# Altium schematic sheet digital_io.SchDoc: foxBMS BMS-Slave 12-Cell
size A3; DocumentNumber: 8; SheetNumber: 8; SheetTotal: 15; AUTHOR: Fraunhofer IISB foxBMS Team; SheetDescription: Primary Digital Inputs/Outputs
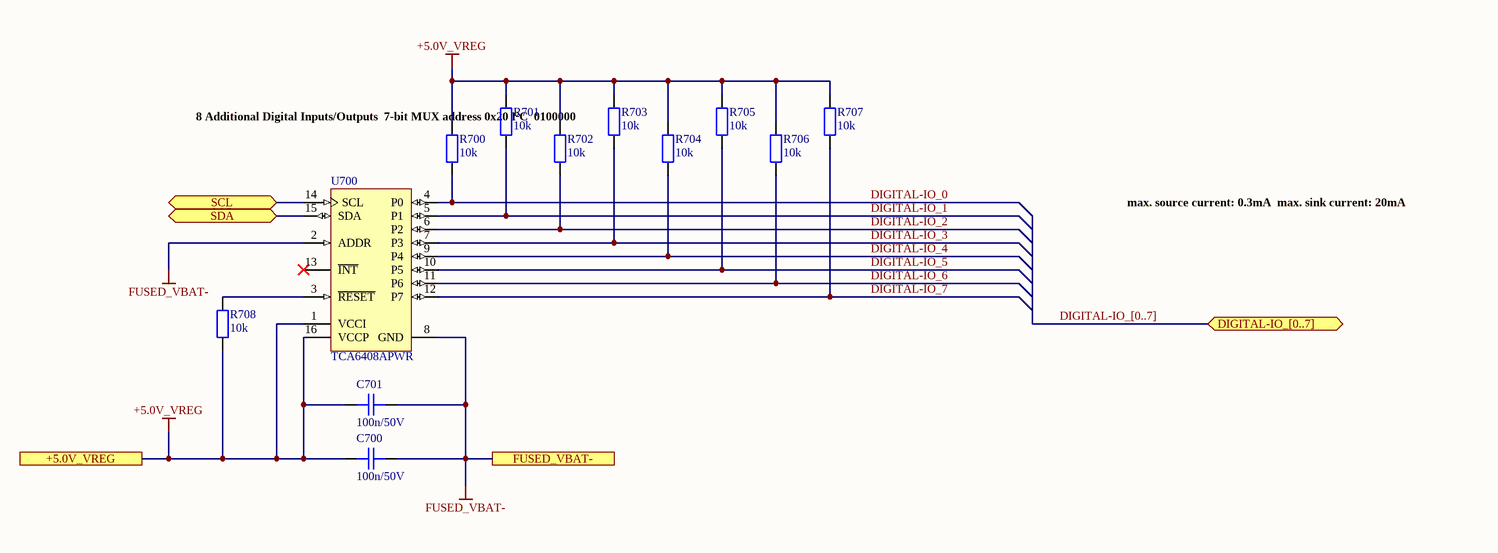
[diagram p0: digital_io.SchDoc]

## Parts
C700  100n/50V  [CAPC1608X08N]
C701  100n/50V  [CAPC1608X08N]
R700  10k  [RESC1608X05N]
R701  10k  [RESC1608X05N]
R702  10k  [RESC1608X05N]
R703  10k  [RESC1608X05N]
R704  10k  [RESC1608X05N]
R705  10k  [RESC1608X05N]
R706  10k  [RESC1608X05N]
R707  10k  [RESC1608X05N]
R708  10k  [RESC1608X05N]
U700  TCA6408APWR  [PW0016A_L]

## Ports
+5.0V_VREG, DIGITAL-IO_[0..7] (bidir), FUSED_VBAT-, SCL (bidir), SDA (bidir)

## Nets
+5.0V_VREG: C700.2 C701.2 R700.2 R701.2 R702.2 R703.2 R704.2 R705.2 R706.2 R707.2 R708.1 U700.1(VCCI) U700.16(VCCP) ; port +5.0V_VREG
FUSED_VBAT-: C700.1 C701.1 U700.2(ADDR) U700.8(GND) ; port FUSED_VBAT-
DIGITAL-IO_0: R700.1 U700.4(P0)
DIGITAL-IO_1: R701.1 U700.5(P1)
DIGITAL-IO_2: R702.1 U700.6(P2)
DIGITAL-IO_3: R703.1 U700.7(P3)
DIGITAL-IO_4: R704.1 U700.9(P4)
DIGITAL-IO_5: R705.1 U700.10(P5)
DIGITAL-IO_6: R706.1 U700.11(P6)
DIGITAL-IO_7: R707.1 U700.12(P7)
SCL: U700.14(SCL) ; port SCL
SDA: U700.15(SDA) ; port SDA
NetR708_2: R708.2 U700.3(~{RESET})

Not connected (* = marked no-connect by the designer): U700 13(~{INT})*

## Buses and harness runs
bus DIGITAL-IO_[0..7] = port DIGITAL-IO_[0..7]

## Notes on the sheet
- 8 Additional Digital Inputs/Outputs
  7-bit MUX address 0x20 I²C
  0100000
- max. source current: 0.3mA
  max. sink current: 20mA

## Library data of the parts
C700 C701 = gen_C_ceramic_100n_50V_X7R_0603: MLCC; Capacitance: 100n; Rated Voltage: 50V; Dielectric: X7R; Case EIA: 0603; Case Metric: 1608; PnP Package: C_0603_10; PnP Value: 100n/50V/X7R; PnP equipped: x; Automotive Qualified: True
R700-R708 = gen_R_10k_0603: SMD Resistor 10k 0603; Tolerance: 1%; Power: 0.1W; Case EIA: 0603; Case Metric: 1608; Maximum Working Voltage: 75V; PnP Package: R_0603; Automotive Qualified: True
U700 = CMP-0314-00338-2: Low-Voltage 8-Bit I2C and SMBus I/O Expander, 1.65 to 5.5 V, -40 to 85 degC, 16-pin TSSOP (PW), Green (RoHS & no Sb/Br); Manufacturer: Texas Instruments; Push-Pull I/O Type: Yes; Max Frequency(kHz): 400; No. of Outputs: 8; VCC(Min)(V): 1.65; SubFamily: I2C IO Expander; I2C Address: 0100 00x; VCC(Max)(V): 5.5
